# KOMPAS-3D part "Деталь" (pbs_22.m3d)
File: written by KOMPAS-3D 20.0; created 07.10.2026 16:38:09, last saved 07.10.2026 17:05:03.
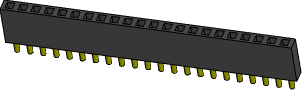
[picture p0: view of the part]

Document properties: Полное имя файла: D:\myProjects\Progect_esp32\box_compas\pbs_22.m3d

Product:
- Part/product: Деталь
    Масса: 0.00672836

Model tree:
1. Эскиз:1
2. Элемент выдавливания:1
     Расстояние 1 = 8.5
3. Эскиз:2  (with: Элемент выдавливания:1)
4. Элемент выдавливания:2
     Расстояние 1 = 3
5. Массив по сетке:2  (with: Элемент выдавливания:2, Эскиз:2)  (22 pattern instances)
     Шаг 1 = 2.54; Угол раствора = 90
6. Эскиз:3  (with: Элемент выдавливания:1)
7. Элемент выдавливания:3
     Расстояние 2 = 8
8. Массив по сетке:3  (with: Элемент выдавливания:3, Эскиз:3)  (22 pattern instances)
     Шаг 1 = 2.54; Угол раствора = 90; Геометрический массив = 128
